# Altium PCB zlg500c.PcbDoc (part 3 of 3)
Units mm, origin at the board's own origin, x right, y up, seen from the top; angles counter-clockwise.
Board outline 135.13 x 130.56 mm, 2 copper layers (Top Layer, Bottom Layer); 79 components, 87 nets, 356 pads, 44 vias.
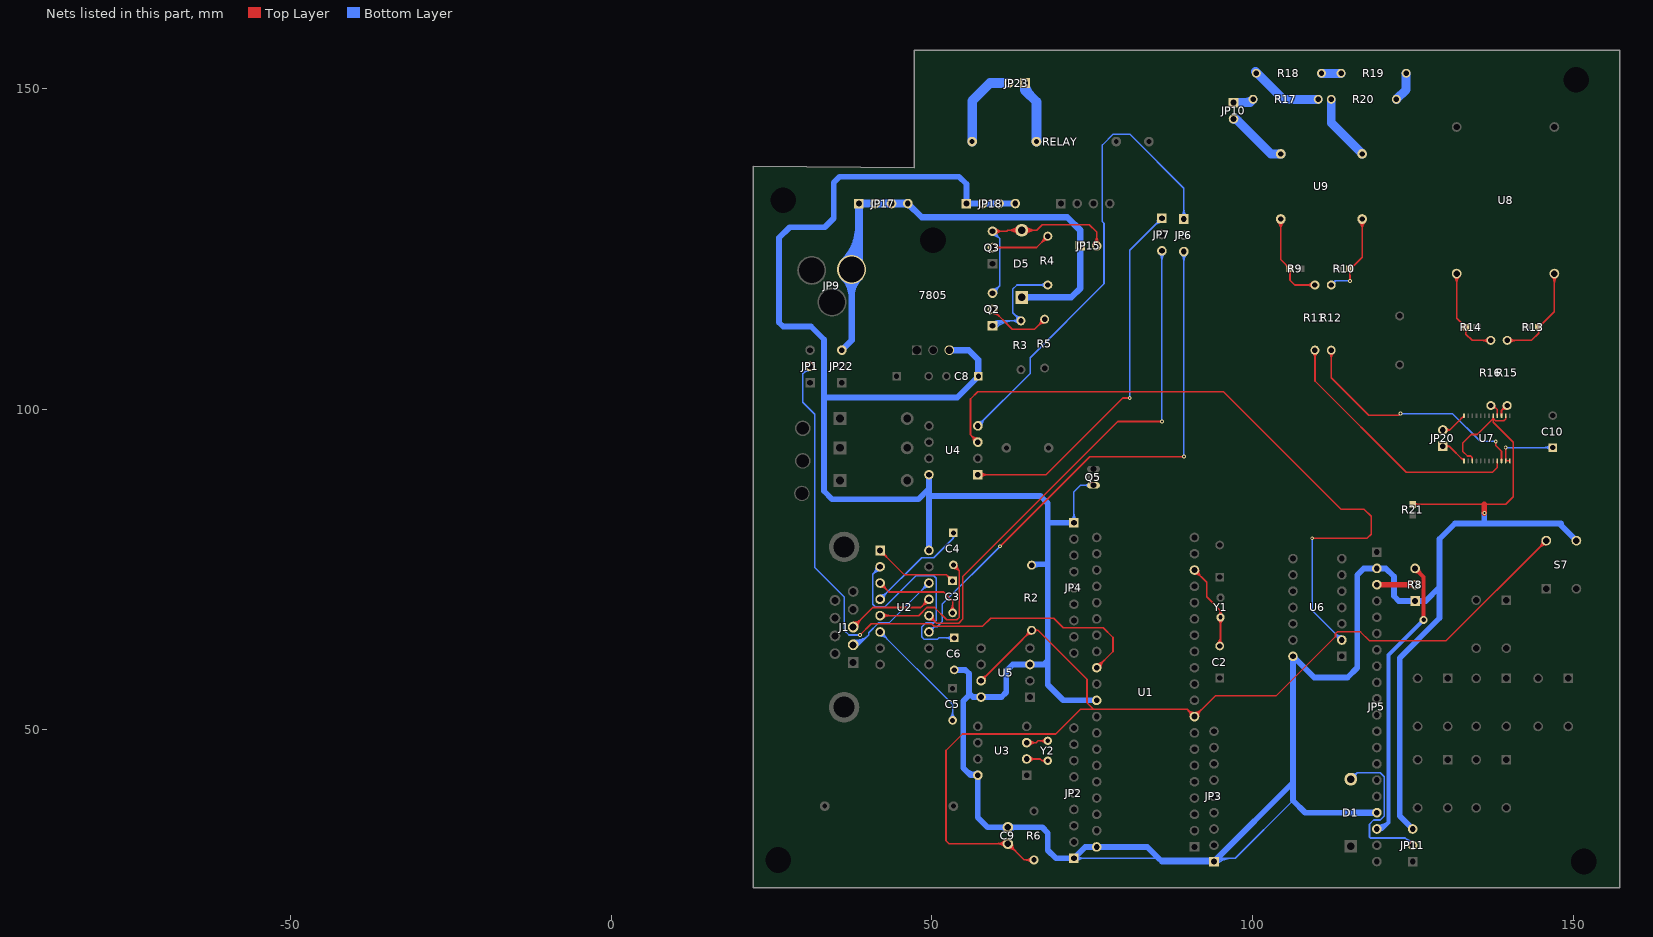
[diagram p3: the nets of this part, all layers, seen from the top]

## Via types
v1: diameter 0.6, hole 0.3, Top Layer to Bottom Layer, 43 vias
v2: diameter 1.27, hole 0.711, Top Layer to Bottom Layer, 1 vias

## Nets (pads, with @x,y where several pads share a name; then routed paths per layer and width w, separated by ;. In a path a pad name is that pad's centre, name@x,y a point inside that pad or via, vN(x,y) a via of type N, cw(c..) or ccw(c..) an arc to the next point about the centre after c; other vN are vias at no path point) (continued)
NetC2_2: C2.2 U1.18 Y1.2 | length 23.8
  Top Layer w0.254: U1.18@90.932,74.307 cw(c90.932,72.803) 91.996,73.866 cw(c93.059,74.93) U1.18@91.555,74.93 ; U1.18@90.932,74.561 cw(c90.932,73.67) 91.562,74.3 cw(c92.192,74.93) U1.18@91.301,74.93 ; U1.18@90.932,74.93 92.837,73.025 92.837,70.739 94.996,68.58 ; C2.2@94.482,63.467 ccw(c93.239,64.709) 94.996,64.709 ; Y1.2@94.626,67.168 cw(c93.733,66.275) 94.996,66.275 cw(c96.259,66.275) Y1.2@95.366,67.168 ; C2.2@94.661,63.287 ccw(c93.853,64.095) 94.996,64.095 ccw(c95.885,64.095) C2.2@95.256,63.467 ; Y1.2@94.684,67.957 ccw(c94.22,68.58) 94.996,68.58 ; C2.2@94.869,63.079 94.869,63.206 94.996,63.206 Y1.2@94.996,67.538 94.996,68.58 ; Y1.2@95.308,67.957 cw(c95.772,68.58) 94.996,68.58
NetC3_1: C3.1 U2.1 | length 20.2
  Top Layer w0.254: U2.1@41.91,77.355 cw(c41.91,75.851) 42.974,76.914 cw(c44.037,77.978) U2.1@42.533,77.978 ; U2.1@41.91,77.609 cw(c41.91,76.718) 42.54,77.348 cw(c43.17,77.978) U2.1@42.279,77.978 ; U2.1@41.91,77.978 45.72,74.168 52.284,74.168 ; C3.1@52.665,73.242 ccw(c51.364,73.248) 52.284,74.168 ; C3.1@52.919,73.24 ccw(c52.221,73.244) 52.715,73.737 ccw(c53.208,74.231) C3.1@53.212,73.533 ; C3.1@53.21,73.787 cw(c53.204,75.088) 52.284,74.168 ; C3.1@53.213,73.239 52.284,74.168
NetC3_2: C3.2 U2.3 | length 24.5
  Top Layer w0.254: U2.3@41.91,72.275 cw(c41.91,70.771) 42.974,71.834 cw(c44.037,72.898) U2.3@42.533,72.898 ; U2.3@41.91,72.529 cw(c41.91,71.638) 42.54,72.268 cw(c43.17,72.898) U2.3@42.279,72.898 ; U2.3@41.91,72.898 43.307,71.501 51.816,71.501 53.213,70.104 C3.2@53.213,68.239 ; 53.213,68.949 cw(c52.503,68.949) 53.005,68.447 ccw(c52.503,68.949) 53.213,68.949 ; 53.213,68.949 ccw(c53.923,68.949) 53.421,68.447 cw(c53.923,68.949) 53.213,68.949 ; 53.213,69.562 cw(c51.89,69.562) 52.826,68.626 ccw(c51.89,69.562) 53.213,69.562 ; 53.213,69.562 ccw(c54.536,69.562) 53.6,68.626 cw(c54.536,69.562) 53.213,69.562
NetC4_1: C4.1 U2.4 | length 21.7
  Bottom Layer w0.254: U2.4@41.91,70.358 48.387,76.835 50.292,76.835 53.34,79.883 ; U2.4@41.91,70.727 ccw(c41.91,71.618) 42.54,70.988 ccw(c43.17,70.358) U2.4@42.279,70.358 ; U2.4@41.91,70.981 ccw(c41.91,72.485) 42.974,71.422 ccw(c44.037,70.358) U2.4@42.533,70.358 ; C4.1@53.34,80.732 53.34,79.883 ; 53.34,79.883 cw(c53.724,79.883) 53.566,80.233 ccw(c53.724,79.883) 53.34,79.883 ; 53.34,79.883 ccw(c52.956,79.883) 53.114,80.233 cw(c52.956,79.883) 53.34,79.883
NetC4_2: C4.2 U2.5 | length 33.1
  Top Layer w0.254: U2.5@41.91,67.818 47.93,67.818 49.2,69.088 50.394,69.088 52.324,67.158 53.873,67.158 54.28,67.564 54.28,74.792 C4.2@53.34,75.732 ; C4.2@53.34,75.184 cw(c53.34,73.861) 54.275,74.796 cw(c55.211,75.732) C4.2@53.888,75.732 ; C4.2@53.34,75.438 cw(c53.34,74.728) 53.842,75.23 cw(c54.344,75.732) C4.2@53.634,75.732 ; 42.801,67.818 cw(c42.801,68.709) 42.171,68.079 ccw(c42.801,68.709) 42.801,67.818 ; 42.801,67.818 ccw(c42.801,66.927) 42.171,67.557 cw(c42.801,66.927) 42.801,67.818 ; 43.414,67.818 cw(c43.414,69.322) 42.351,68.259 ccw(c43.414,69.322) 43.414,67.818 ; 43.414,67.818 ccw(c43.414,66.314) 42.351,67.377 cw(c43.414,66.314) 43.414,67.818
NetC5_2: C5.2 U2.6 | length 25.4
  Bottom Layer w0.254: U2.6@41.91,64.655 cw(c41.91,63.151) 42.974,64.214 cw(c44.037,65.278) U2.6@42.533,65.278 ; U2.6@41.91,64.909 cw(c41.91,64.018) 42.54,64.648 cw(c43.17,65.278) U2.6@42.279,65.278 ; U2.6@41.91,65.278 53.213,53.975 C5.2@53.213,51.475 ; C5.2@52.826,51.862 ccw(c51.89,52.798) 53.213,52.798 ccw(c54.536,52.798) C5.2@53.6,51.862 ; C5.2@53.005,51.683 ccw(c52.503,52.185) 53.213,52.185 ccw(c53.923,52.185) C5.2@53.421,51.683
NetC6_1: C6.1 U2.2 | length 41.7
  Bottom Layer w0.254: U2.2@41.287,75.438 cw(c39.783,75.438) 40.846,74.374 cw(c41.91,73.311) U2.2@41.91,74.815 ; U2.2@41.541,75.438 cw(c40.65,75.438) 41.28,74.808 cw(c41.91,74.178) U2.2@41.91,75.069 ; U2.2@41.91,75.438 40.767,74.295 40.767,69.596 41.148,69.215 42.672,69.215 47.498,74.041 50.292,74.041 50.673,73.66 50.673,67.056 50.292,66.675 49.022,66.675 48.387,66.04 48.387,64.516 48.768,64.135 50.876,64.135 51.09,64.349 C6.1@53.467,64.349 ; C6.1@53.08,63.962 ccw(c52.144,63.026) 52.144,64.349 ccw(c52.144,65.672) C6.1@53.08,64.737 ; C6.1@53.259,64.141 ccw(c52.757,63.639) 52.757,64.349 ccw(c52.757,65.059) C6.1@53.259,64.557
NetC10_1: C10.1 U7.11 U7.12 | length 16.5
  Top Layer w0.254: v1(139.469,94.02) U7.11@139.469,91.948 U7.12@140.119,91.948
  Bottom Layer w0.254: v1(139.469,94.02) C10.1@146.812,94.02 ; 145.489,94.02 cw(c145.489,92.697) 146.425,93.632 ccw(c145.489,92.697) 145.489,94.02 ; 145.489,94.02 ccw(c145.489,95.343) 146.425,94.407 cw(c145.489,95.343) 145.489,94.02 ; 146.102,94.02 cw(c146.102,93.31) 146.604,93.812 ccw(c146.102,93.31) 146.102,94.02 ; 146.102,94.02 ccw(c146.102,94.73) 146.604,94.228 cw(c146.102,94.73) 146.102,94.02
NetD1_1: D1.1 JP11.2 | length 34.7
  Bottom Layer w0.254: D1.1@115.316,42.314 116.309,43.307 ; JP11.2@124.968,32.004 123.825,33.147 118.364,33.147 118.237,33.274 118.237,35.306 118.872,35.941 119.888,35.941 120.523,36.576 120.523,42.672 119.888,43.307 116.309,43.307 ; 116.309,43.307 cw(c115.819,43.797) 115.596,43.141 ccw(c115.819,43.797) 116.309,43.307 ; 116.309,43.307 ccw(c116.799,42.817) 116.143,42.594 cw(c116.799,42.817) 116.309,43.307 ; 123.904,33.068 cw(c122.841,32.004) 124.345,32.004 ccw(c122.841,32.004) 123.904,33.068 ; 123.904,33.068 ccw(c124.968,34.131) 124.968,32.627 cw(c124.968,34.131) 123.904,33.068 ; 124.338,32.634 cw(c123.708,32.004) 124.599,32.004 ccw(c123.708,32.004) 124.338,32.634 ; 124.338,32.634 ccw(c124.968,33.264) 124.968,32.373 cw(c124.968,33.264) 124.338,32.634
NetD5_1: D5.1 JP15.2 Q2.3 Q3.3 | length 56.3
  Top Layer w0.254: Q3.3@59.436,127.762 61.646,127.762 61.796,127.912 D5.1@64.008,127.912 66.317,127.912 67.183,128.778 74.549,128.778 75.692,127.635 JP15.2@75.692,125.476 ; Q3.3@59.697,127.501 cw(c60.327,126.871) 60.327,127.762 cw(c60.327,128.653) Q3.3@59.697,128.023 ; Q3.3@59.877,127.321 cw(c60.94,126.258) 60.94,127.762 cw(c60.94,129.266) Q3.3@59.877,128.203 ; D5.1@63.391,127.295 ccw(c61.9,125.804) 61.9,127.912 ccw(c61.9,130.02) D5.1@63.391,128.529 ; D5.1@63.57,127.474 ccw(c62.514,126.418) 62.514,127.912 ccw(c62.514,129.406) D5.1@63.57,128.35 ; D5.1@64.446,127.474 cw(c65.502,126.418) 65.502,127.912 cw(c65.502,129.406) D5.1@64.446,128.35 ; D5.1@64.625,127.295 cw(c66.116,125.804) 66.116,127.912 cw(c66.116,130.02) D5.1@64.625,128.529 ; JP15.2@75.251,125.917 ccw(c74.188,126.98) 75.692,126.98 ccw(c77.196,126.98) JP15.2@76.133,125.917 ; JP15.2@75.431,125.737 ccw(c74.801,126.367) 75.692,126.367 ccw(c76.583,126.367) JP15.2@75.953,125.737
  Bottom Layer w0.254: Q2.3@59.436,118.11 60.579,119.253 60.579,126.619 Q3.3@59.436,127.762 ; Q2.3@59.436,118.479 ccw(c59.436,119.37) 60.066,118.74 ccw(c60.696,118.11) Q2.3@59.805,118.11 ; Q2.3@59.436,118.733 ccw(c59.436,120.237) 60.5,119.174 ccw(c61.563,118.11) Q2.3@60.059,118.11 ; Q3.3@59.436,127.139 cw(c59.436,125.635) 60.5,126.698 cw(c61.563,127.762) Q3.3@60.059,127.762 ; Q3.3@59.436,127.393 cw(c59.436,126.502) 60.066,127.132 cw(c60.696,127.762) Q3.3@59.805,127.762
NetJP1_2: JP1.2 U1.29 | length 106.2
  Top Layer w0.254: v1(38.786,64.795) 40.538,66.548 49.936,66.548 50.343,66.142 57.887,66.142 59.157,67.412 68.986,67.412 70.485,65.913 76.733,65.913 78.232,64.414 78.232,62.23 U1.29@75.692,59.69 ; 76.322,60.32 cw(c75.692,60.95) 75.692,60.059 ccw(c75.692,60.95) 76.322,60.32 ; 76.322,60.32 ccw(c76.952,59.69) 76.061,59.69 cw(c76.952,59.69) 76.322,60.32 ; 76.756,60.754 cw(c75.692,61.817) 75.692,60.313 ccw(c75.692,61.817) 76.756,60.754 ; 76.756,60.754 ccw(c77.819,59.69) 76.315,59.69 cw(c77.819,59.69) 76.756,60.754
  Bottom Layer w0.254: JP1.2@30.365,106.68 cw(c28.861,106.68) 29.924,105.616 cw(c30.988,104.553) JP1.2@30.988,106.057 ; JP1.2@30.619,106.68 cw(c29.728,106.68) 30.358,106.05 cw(c30.988,105.42) JP1.2@30.988,106.311 ; JP1.2@30.988,106.68 29.845,105.537 29.845,101.117 31.725,99.238 31.725,75.311 36.322,70.714 36.322,65.532 37.059,64.795 v1(38.786,64.795)
NetJP10_1: JP10.1 R17.2 | length 25.1
  Bottom Layer w0.254: JP10.1@97.028,147.828 97.536,148.336 R17.2@100.076,148.336 ; R17.2@99.671,147.931 ccw(c98.693,146.953) 98.693,148.336 ccw(c98.693,149.719) R17.2@99.671,148.741 ; R17.2@99.85,148.11 ccw(c99.306,147.566) 99.306,148.336 ccw(c99.306,149.106) R17.2@99.85,148.562 ; JP10.1@96.93,147.926 cw(c97.919,146.937) 97.919,148.336 ccw(c97.919,146.937) JP10.1@96.93,147.926 ; JP10.1@97.109,147.747 cw(c98.532,146.324) 98.532,148.336 ccw(c98.532,146.324) JP10.1@97.109,147.747 ; JP10.1@97.289,147.567 cw(c99.145,145.711) 99.145,148.336 ccw(c99.145,145.711) JP10.1@97.289,147.567 ; JP10.1@97.469,147.387 cw(c99.758,145.098) 99.758,148.336 ccw(c99.758,145.098) JP10.1@97.469,147.387
  Bottom Layer w1.4: JP10.1@97.028,147.828 99.568,147.828 ; 98.85,147.828 ccw(c98.85,149.562) R17.2@100.076,148.336
NetJP10_2: JP10.2 U9.2 | length 11.3
  Bottom Layer w1.4: JP10.2@97.028,145.288 97.409,145.288 102.87,139.827 U9.2@104.394,139.827 ; JP10.2@97.028,145.238 cw(c97.028,144.197) 97.764,144.933 ccw(c97.028,144.197) JP10.2@97.028,145.238
NetJP20_1: JP20.1 U7.1 | length 7.5
  Top Layer w0.254: JP20.1@129.667,94.234 130.683,94.234 ; U7.1@132.969,91.948 130.683,94.234 ; 130.683,94.234 cw(c130.683,94.751) 130.222,94.517 ccw(c130.683,94.751) 130.683,94.234 ; 130.683,94.234 ccw(c130.683,93.717) 130.222,93.951 cw(c130.683,93.717) 130.683,94.234 ; 132.546,92.371 ccw(c132.969,92.795) 132.969,92.196 cw(c132.969,92.795) 132.546,92.371
NetJP20_2: JP20.2 U7.24 | length 7.8
  Top Layer w0.254: JP20.2@129.667,96.774 130.745,96.774 ; U7.24@132.969,98.998 130.745,96.774 ; 130.745,96.774 cw(c130.745,97.395) 130.207,97.085 ccw(c130.745,97.395) 130.745,96.774 ; 130.745,96.774 ccw(c130.745,96.153) 130.207,96.463 cw(c130.745,96.153) 130.745,96.774 ; 132.546,98.575 cw(c132.969,98.151) 132.969,98.75 ccw(c132.969,98.151) 132.546,98.575
NetJP23_1: JP23.1 RELAY.2 | length 12
  Bottom Layer w1.5: 65.324,148.925 cw(c67.275,150.876) JP23.1@64.516,150.876 64.516,149.733 66.294,147.955 RELAY.2@66.294,141.732
NetJP23_2: JP23.2 RELAY.3 | length 13.2
  Bottom Layer w1.5: RELAY.3@56.261,141.732 56.261,148.082 59.055,150.876 JP23.2@61.976,150.876
NetQ2_1: Q2.1 R3.2 R4.2 | length 40
  Bottom Layer w0.254: Q2.1@59.158,113.308 cw(c60.327,112.139) 60.327,113.792 ; Q2.1@59.338,113.128 cw(c60.94,111.526) 60.94,113.792 ; Q2.1@59.436,113.03 60.198,113.792 ; Q2.1@59.517,112.949 cw(c61.553,110.913) 61.553,113.792 ; Q2.1@59.697,112.769 cw(c62.166,110.3) 62.166,113.792 ; Q2.1@59.877,112.589 cw(c62.78,109.686) 62.78,113.792 ; R3.2@63.308,113.792 ccw(c61.925,113.792) 62.903,114.77 ccw(c63.881,115.748) R3.2@63.881,114.365 ; R3.2@63.476,113.387 ccw(c62.498,112.409) 62.498,113.792 ccw(c62.498,115.175) R3.2@63.476,114.197 ; R3.2@63.562,113.792 ccw(c62.792,113.792) 63.336,114.337 ccw(c63.881,114.881) R3.2@63.881,114.111 ; R3.2@63.655,113.566 ccw(c63.111,113.022) 63.111,113.792 ccw(c63.111,114.562) R3.2@63.655,114.018 ; R4.2@67.667,118.975 ccw(c66.689,117.997) 66.689,119.38 ccw(c66.689,120.763) R4.2@67.667,119.785 ; R4.2@67.846,119.154 ccw(c67.302,118.61) 67.302,119.38 ccw(c67.302,120.15) R4.2@67.846,119.606 ; R4.2@68.072,119.38 63.246,119.38 62.611,118.745 62.611,115.062 R3.2@63.881,113.792 60.198,113.792 ; 60.198,113.792 cw(c59.759,114.231) 59.598,113.632 ccw(c59.759,114.231) 60.198,113.792 ; 60.198,113.792 ccw(c60.637,113.353) 60.038,113.192 cw(c60.637,113.353) 60.198,113.792
NetQ2_2: Q2.2 R5.1 | length 17.2
  Top Layer w0.254: Q2.2@59.436,114.947 cw(c59.436,113.443) 60.5,114.506 cw(c61.563,115.57) Q2.2@60.059,115.57 ; Q2.2@59.436,115.201 cw(c59.436,114.31) 60.066,114.94 cw(c60.696,115.57) Q2.2@59.805,115.57 ; Q2.2@59.436,115.57 62.535,112.471 65.989,112.471 R5.1@67.564,114.046 ; R5.1@66.991,114.046 cw(c65.608,114.046) 66.586,113.068 cw(c67.564,112.09) R5.1@67.564,113.473 ; R5.1@67.245,114.046 cw(c66.475,114.046) 67.019,113.501 cw(c67.564,112.957) R5.1@67.564,113.727
NetQ3_2: Q3.2 R4.1 | length 16.5
  Top Layer w0.254: Q3.2@59.436,125.222 66.294,125.222 R4.1@68.072,127 ; Q3.2@59.697,124.961 cw(c60.327,124.331) 60.327,125.222 cw(c60.327,126.113) Q3.2@59.697,125.483 ; Q3.2@59.877,124.781 cw(c60.94,123.718) 60.94,125.222 cw(c60.94,126.726) Q3.2@59.877,125.663 ; R4.1@67.499,127 cw(c66.116,127) 67.094,126.022 cw(c68.072,125.044) R4.1@68.072,126.427 ; R4.1@67.753,127 cw(c66.983,127) 67.527,126.455 cw(c68.072,125.911) R4.1@68.072,126.681
NetR9_1: R9.1 R11.1 U9.3 | length 24.4
  Top Layer w0.254: U9.3@103.945,129.218 cw(c102.861,128.134) 104.394,128.134 cw(c105.927,128.134) U9.3@104.843,129.218 ; U9.3@104.125,129.398 cw(c103.474,128.747) 104.394,128.747 cw(c105.314,128.747) U9.3@104.663,129.398 ; U9.3@104.394,129.667 104.394,123.356 R9.1@105.83,121.92 105.83,120.103 106.553,119.38 R11.1@109.728,119.38 ; 105.108,122.642 cw(c104.386,121.92) R9.1@105.407,121.92 ; 105.229,122.521 ccw(c105.78,123.073) R9.1@105.78,122.293 ; R9.1@105.566,121.656 cw(c104.93,121.02) 105.83,121.02 cw(c106.731,121.02) R9.1@106.094,121.656 ; R11.1@109.323,118.975 ccw(c108.345,117.997) 108.345,119.38 ccw(c108.345,120.763) R11.1@109.323,119.785 ; R11.1@109.502,119.154 ccw(c108.958,118.61) 108.958,119.38 ccw(c108.958,120.15) R11.1@109.502,119.606
NetR10_2: R10.2 R12.1 U9.4 | length 21.9
  Top Layer w0.254: v1(115.189,120.015) R10.2@115.15,121.92 115.316,121.92 117.094,123.698 U9.4@117.094,129.667 ; R10.2@115.2,122.293 ccw(c115.2,123.474) 116.035,122.639 ; R10.2@115.573,121.92 cw(c116.193,121.92) 115.755,122.359 ; U9.4@116.645,129.218 cw(c115.561,128.134) 117.094,128.134 cw(c118.627,128.134) U9.4@117.543,129.218 ; U9.4@116.825,129.398 cw(c116.174,128.747) 117.094,128.747 cw(c118.014,128.747) U9.4@117.363,129.398 ; 115.161,121.383 cw(c115.34,121.386) 115.294,121.559 ccw(c115.34,121.386) 115.161,121.383 ; 115.161,121.383 ccw(c114.927,121.378) 115.032,121.587 cw(c114.927,121.378) 115.161,121.383
  Bottom Layer w0.254: R12.1@112.268,119.38 112.903,120.015 ; v1(115.189,120.015) 112.903,120.015 ; 112.903,120.015 cw(c112.608,120.31) 112.465,119.918 ccw(c112.608,120.31) 112.903,120.015 ; 112.903,120.015 ccw(c113.198,119.72) 112.806,119.577 cw(c113.198,119.72) 112.903,120.015
NetR11_2: R11.2 U7.9 | length 43.9
  Top Layer w0.254: R11.2@109.323,108.815 cw(c108.345,107.837) 109.728,107.837 cw(c111.111,107.837) R11.2@110.133,108.815 ; R11.2@109.502,108.994 cw(c108.958,108.45) 109.728,108.45 cw(c110.498,108.45) R11.2@109.954,108.994 ; R11.2@109.728,109.22 109.728,104.394 123.952,90.17 137.414,90.17 138.169,90.925 U7.9@138.169,91.948
NetR12_2: R12.2 U7.10 | length 41.1
  Top Layer w0.254: R12.2@111.863,108.815 cw(c110.885,107.837) 112.268,107.837 cw(c113.651,107.837) R12.2@112.673,108.815 ; R12.2@112.042,108.994 cw(c111.498,108.45) 112.268,108.45 cw(c113.038,108.45) R12.2@112.494,108.994 ; R12.2@112.268,109.22 112.268,104.902 118.11,99.06 122.809,99.06 v1(123.063,99.314) ; v1(137.922,94.996) 137.922,94.361 138.819,93.464 U7.10@138.819,91.948
  Bottom Layer w0.254: v1(123.063,99.314) 131.191,99.314 135.509,94.996 v1(137.922,94.996)
NetR13_1: R13.1 R15.1 U8.2 | length 25.9
  Top Layer w0.254: R15.1@139.7,110.744 143.51,110.744 144.614,111.848 R13.1@144.614,112.776 147.066,115.228 U8.2@147.066,121.158 U8.2@147.066,121.285 ; R15.1@139.926,110.518 cw(c140.47,109.974) 140.47,110.744 cw(c140.47,111.514) R15.1@139.926,110.97 ; R15.1@140.105,110.339 cw(c141.083,109.361) 141.083,110.744 cw(c141.083,112.127) R15.1@140.105,111.149 ; R13.1@144.35,112.512 cw(c143.713,111.876) 144.614,111.876 cw(c145.514,111.876) R13.1@144.878,112.512 ; R13.1@144.664,113.149 ccw(c144.664,113.929) 145.215,113.377 ; R13.1@145.037,112.776 cw(c146.058,112.776) 145.336,113.498 ; U8.2@146.617,120.709 cw(c145.533,119.625) 147.066,119.625 cw(c148.599,119.625) U8.2@147.515,120.709 ; U8.2@146.797,120.889 cw(c146.146,120.238) 147.066,120.238 cw(c147.986,120.238) U8.2@147.335,120.889
NetR14_2: R14.2 R16.1 U8.1 | length 24.5
  Top Layer w0.254: U8.1@131.377,120.709 cw(c130.293,119.625) 131.826,119.625 cw(c133.359,119.625) U8.1@132.275,120.709 ; U8.1@131.557,120.889 cw(c130.906,120.238) 131.826,120.238 cw(c132.746,120.238) U8.1@132.095,120.889 ; U8.1@131.826,121.285 U8.1@131.826,121.158 131.826,114.212 R14.2@133.262,112.776 133.262,111.721 134.239,110.744 R16.1@137.16,110.744 ; 132.54,113.498 cw(c131.818,112.776) R14.2@132.839,112.776 ; 132.661,113.377 ccw(c133.212,113.929) R14.2@133.212,113.149 ; R14.2@132.998,112.512 cw(c132.362,111.876) 133.262,111.876 cw(c134.163,111.876) R14.2@133.526,112.512 ; R16.1@136.755,110.339 ccw(c135.777,109.361) 135.777,110.744 ccw(c135.777,112.127) R16.1@136.755,111.149 ; R16.1@136.934,110.518 ccw(c136.39,109.974) 136.39,110.744 ccw(c136.39,111.514) R16.1@136.934,110.97
NetR15_2: R15.2 U7.15 | length 6.7
  Top Layer w0.254: U7.15@138.819,98.998 138.819,99.83 139.573,100.584 R15.2@139.7,100.584 ; 138.756,99.767 cw(c139.413,99.109) 139.59,100.022 ccw(c139.413,99.109) 138.756,99.767 ; 138.812,99.823 ccw(c138.05,100.584) 139.127,100.584 cw(c138.05,100.584) 138.812,99.823 ; 139.093,100.104 cw(c139.523,99.675) 139.639,100.271 ccw(c139.523,99.675) 139.093,100.104
NetR16_2: R16.2 U7.16 | length 4.7
  Top Layer w0.254: R16.2@137.16,100.584 137.541,100.584 138.169,99.956 U7.16@138.169,98.998 ; R16.2@137.249,100.278 cw(c137.476,99.49) 138.055,100.07 ccw(c137.476,99.49) R16.2@137.249,100.278 ; R16.2@137.733,100.584 ccw(c138.197,100.584) 137.869,100.256 cw(c138.197,100.584) R16.2@137.733,100.584
NetR17_1: R17.1 R18.2 | length 11.7
  Bottom Layer w0.254: R18.2@100.559,152.552 100.559,152.4 R18.2@100.584,152.4
  Bottom Layer w1.4: R18.2@100.457,152.654 100.559,152.552 100.647,152.463 104.775,148.336 R17.1@110.236,148.336
NetR18_1: R18.1 R19.2 | length 3
  Bottom Layer w1.4: R18.1@110.744,152.4 R19.2@113.792,152.4
NetR19_1: R19.1 R20.1 | length 5.2
  Top Layer w0.254: R20.1@122.428,148.336 R20.1@122.428,148.844
  Bottom Layer w1.4: R20.1@122.428,148.336 123.952,149.86 R19.1@123.952,152.4
NetR20_2: R20.2 U9.1 | length 10.5
  Bottom Layer w1.4: R20.2@112.268,148.336 112.268,144.653 U9.1@117.094,139.827
NetU3_2: U3.2 Y2.2 | length 13
  Top Layer w0.254: U3.2@64.77,45.466 66.904,45.466 67.184,45.186 Y2.2@68.072,45.186 ; 65.661,45.466 cw(c65.661,46.357) 65.031,45.727 ccw(c65.661,46.357) 65.661,45.466 ; 65.661,45.466 ccw(c65.661,44.575) 65.031,45.205 cw(c65.661,44.575) 65.661,45.466 ; 66.274,45.466 cw(c66.274,46.97) 65.211,45.907 ccw(c66.274,46.97) 66.274,45.466 ; 66.274,45.466 ccw(c66.274,43.962) 65.211,45.025 cw(c66.274,43.962) 66.274,45.466 ; 67.184,45.186 cw(c67.184,44.693) 67.615,44.932 ccw(c67.184,44.693) 67.184,45.186 ; 67.184,45.186 ccw(c67.184,45.679) 67.615,45.44 cw(c67.184,45.679) 67.184,45.186
NetU3_3: U3.3 Y2.1 | length 14.9
  Top Layer w0.254: U3.3@64.77,48.006 66.269,48.006 ; Y2.1@68.072,48.286 66.549,48.286 66.269,48.006 ; 65.658,48.006 cw(c65.658,48.889) 65.032,48.266 ccw(c65.658,48.889) 65.658,48.006 ; 65.658,48.006 ccw(c65.658,47.123) 65.032,47.746 cw(c65.658,47.123) 65.658,48.006 ; 66.269,48.006 cw(c66.269,49.497) 65.212,48.445 ccw(c66.269,49.497) 66.269,48.006 ; 66.269,48.006 ccw(c66.269,46.515) 65.212,47.567 cw(c66.269,46.515) 66.269,48.006 ; 66.809,48.286 cw(c66.809,47.023) 67.702,47.916 ccw(c66.809,47.023) 66.809,48.286 ; 66.809,48.286 ccw(c66.809,49.549) 67.702,48.656 cw(c66.809,49.549) 66.809,48.286
NetU4_3: U4.3 U6.2 | length 119.5
  Top Layer w0.254: U4.3@56.527,94.869 ccw(c55.023,94.869) 56.086,95.933 ccw(c57.15,96.996) U4.3@57.15,95.492 ; U4.3@56.781,94.869 ccw(c55.89,94.869) 56.52,95.499 ccw(c57.15,96.129) U4.3@57.15,95.238 ; U4.3@57.15,94.869 56.007,96.012 56.007,101.6 57.15,102.743 95.453,102.743 113.817,84.379 117.424,84.379 118.491,83.312 118.491,80.518 117.856,79.883 v1(109.296,79.883)
  Bottom Layer w0.254: v1(109.296,79.883) 109.296,68.631 U6.2@113.919,64.008 ; 112.855,65.072 cw(c111.792,64.008) 113.296,64.008 ccw(c111.792,64.008) 112.855,65.072 ; 112.855,65.072 ccw(c113.919,66.135) 113.919,64.631 cw(c113.919,66.135) 112.855,65.072 ; 113.289,64.638 cw(c112.659,64.008) 113.55,64.008 ccw(c112.659,64.008) 113.289,64.638 ; 113.289,64.638 ccw(c113.919,65.268) 113.919,64.377 cw(c113.919,65.268) 113.289,64.638
PC-RXD: J1.2 U2.14 | length 29.9
  Bottom Layer w0.254: J1.2@37.682,62.974 ccw(c37.818,64.139) 38.648,63.31 ; J1.2@37.712,63.226 ccw(c37.896,64.803) 39.019,63.681 ; J1.2@37.717,63.27 38.608,63.27 ; J1.2@37.741,63.479 ccw(c37.973,65.468) 39.39,64.052 ; J1.2@37.771,63.731 ccw(c38.051,66.133) 39.761,64.423 ; J1.2@37.8,63.983 ccw(c38.129,66.797) 40.132,64.794 ; U2.14@48.907,72.898 cw(c47.403,72.898) 48.466,71.834 cw(c49.53,70.771) U2.14@49.53,72.275 ; U2.14@49.161,72.898 cw(c48.27,72.898) 48.9,72.268 cw(c49.53,71.638) U2.14@49.53,72.529 ; U2.14@49.53,72.898 43.307,66.675 41.656,66.675 40.132,65.151 40.132,64.794 ; 38.608,63.27 cw(c38.608,63.464) 38.419,63.423 ccw(c38.608,63.464) 38.608,63.27 ; 38.608,63.27 ccw(c38.608,63.076) 38.419,63.117 cw(c38.608,63.076) 38.608,63.27 ; 38.608,63.27 40.132,64.794
PC-TXD: J1.3 U2.13 | length 21.8
  Top Layer w0.254: J1.3@37.717,66.04 40.765,69.088 48.26,69.088 U2.13@49.53,70.358 ; J1.3@37.717,66.504 ccw(c37.717,67.624) 38.509,66.832 ccw(c39.301,66.04) J1.3@38.181,66.04 ; J1.3@37.717,66.758 ccw(c37.717,68.491) 38.943,67.266 ccw(c40.168,66.04) J1.3@38.435,66.04 ; U2.13@48.907,70.358 cw(c47.403,70.358) 48.466,69.294 cw(c49.53,68.231) U2.13@49.53,69.735 ; U2.13@49.161,70.358 cw(c48.27,70.358) 48.9,69.728 cw(c49.53,69.098) U2.13@49.53,69.989
RESET: C9.1 R2.1 R6.2 S7.4 U1.9 U5.7 | length 213.1
  Top Layer w0.254: U5.7@57.658,57.658 58.547,58.547 ; U5.7@57.742,58.275 ccw(c57.87,59.224) 58.547,58.547 ; U5.7@58.275,57.742 cw(c59.224,57.87) 58.547,58.547 ; C9.1@61.355,31.764 ccw(c60.164,30.573) 60.164,32.258 ccw(c60.164,33.943) C9.1@61.355,32.752 ; C9.1@61.535,31.944 ccw(c60.777,31.186) 60.777,32.258 ccw(c60.777,33.33) C9.1@61.535,32.572 ; C9.1@61.849,31.56 cw(c61.849,29.875) 63.041,31.066 cw(c64.232,32.258) C9.1@62.547,32.258 ; C9.1@61.849,31.814 cw(c61.849,30.742) 62.607,31.5 cw(c63.365,32.258) C9.1@62.293,32.258 ; 64.135,64.084 58.623,58.572 ; R2.1@64.959,65.532 cw(c63.576,65.532) 64.554,64.554 cw(c65.532,63.576) R2.1@65.532,64.959 ; R2.1@65.213,65.532 cw(c64.443,65.532) 64.987,64.987 cw(c65.532,64.443) R2.1@65.532,65.213 ; R6.2@65.508,29.313 ccw(c64.53,28.335) 64.53,29.718 ccw(c64.53,31.101) R6.2@65.508,30.123 ; R6.2@65.687,29.492 ccw(c65.143,28.948) 65.143,29.718 ccw(c65.143,30.488) R6.2@65.687,29.944 ; R6.2@65.913,29.718 64.389,29.718 C9.1@61.849,32.258 52.654,32.258 52.197,32.715 52.197,46.787 54.762,49.352 69.291,49.352 73.152,53.213 75.184,53.213 ; S7.4@145.161,79.502 cw(c143.628,79.502) 144.712,78.418 cw(c145.796,77.334) S7.4@145.796,78.867 ; S7.4@145.415,79.502 cw(c144.495,79.502) 145.146,78.852 cw(c145.796,78.201) S7.4@145.796,79.121 ; S7.4@145.796,79.502 130.175,63.881 118.237,63.881 116.84,65.278 113.182,65.278 112.928,65.024 112.928,64.565 103.659,55.296 94.158,55.296 U1.9@90.932,52.07 89.789,53.213 75.184,53.213 ; 58.547,58.547 58.598,58.547 58.623,58.572 ; 58.623,58.572 58.598,58.598 R2.1@65.532,65.532 66.548,65.532 ; 66.548,65.532 cw(c66.548,66.146) 66.022,65.828 ccw(c66.548,66.146) 66.548,65.532 ; 66.548,65.532 ccw(c66.548,64.918) 66.022,65.236 cw(c66.548,64.918) 66.548,65.532 ; 66.548,65.532 74.168,57.912 74.168,54.229 75.184,53.213 ; 89.868,53.134 cw(c88.805,52.07) 90.309,52.07 ccw(c88.805,52.07) 89.868,53.134 ; 89.868,53.134 ccw(c90.932,54.197) U1.9@90.932,52.693 ; 89.868,53.134 ccw(c90.932,54.197) U1.9@90.932,52.693 ; 90.302,52.7 cw(c89.672,52.07) 90.563,52.07 ccw(c89.672,52.07) 90.302,52.7 ; 90.302,52.7 ccw(c90.932,53.33) U1.9@90.932,52.439 ; 90.302,52.7 ccw(c90.932,53.33) U1.9@90.932,52.439 ; U1.9@90.932,52.439 ccw(c90.932,53.33) 91.562,52.7 ; U1.9@90.932,52.439 ccw(c90.932,53.33) 91.562,52.7 ; U1.9@90.932,52.693 ccw(c90.932,54.197) 91.996,53.134 ; U1.9@90.932,52.693 ccw(c90.932,54.197) 91.996,53.134 ; 91.562,52.7 ccw(c92.192,52.07) 91.301,52.07 cw(c92.192,52.07) 91.562,52.7 ; 91.996,53.134 ccw(c93.059,52.07) 91.555,52.07 cw(c93.059,52.07) 91.996,53.134
RS-232R: JP7.3 U2.12 | length 91.6
  Top Layer w0.254: U2.12@49.53,67.818 50.698,66.65 54.153,66.65 54.788,67.285 54.788,73.914 78.969,98.095 v1(85.852,98.095) ; 50.16,67.188 cw(c50.79,67.818) 49.899,67.818 ccw(c50.79,67.818) 50.16,67.188 ; 50.16,67.188 ccw(c49.53,66.558) 49.53,67.449 cw(c49.53,66.558) 50.16,67.188 ; 50.594,66.754 cw(c51.657,67.818) 50.153,67.818 ccw(c51.657,67.818) 50.594,66.754 ; 50.594,66.754 ccw(c49.53,65.691) 49.53,67.195 cw(c49.53,65.691) 50.594,66.754
  Bottom Layer w0.254: JP7.3@85.411,124.273 cw(c84.348,123.21) 85.852,123.21 cw(c87.356,123.21) JP7.3@86.293,124.273 ; JP7.3@85.591,124.453 cw(c84.961,123.823) 85.852,123.823 cw(c86.743,123.823) JP7.3@86.113,124.453 ; v1(85.852,98.095) JP7.3@85.852,124.714
RS-232T: JP6.3 U2.11 | length 93.7
  Top Layer w0.254: v1(60.63,78.638) 74.6,92.608 v1(89.281,92.608)
  Bottom Layer w0.254: U2.11@49.53,65.278 50.343,66.091 ; U2.11@49.659,65.888 ccw(c49.813,66.62) 50.343,66.091 ; U2.11@50.14,65.407 cw(c50.872,65.561) 50.343,66.091 ; v1(60.63,78.638) 51.613,69.621 51.613,66.904 50.8,66.091 50.343,66.091 ; v1(89.281,92.608) JP6.3@89.281,124.587 ; 89.281,123.083 cw(c90.785,123.083) 89.722,124.146 ccw(c90.785,123.083) 89.281,123.083 ; 89.281,123.083 ccw(c87.777,123.083) 88.84,124.146 cw(c87.777,123.083) 89.281,123.083 ; 89.281,123.696 cw(c90.172,123.696) 89.542,124.326 ccw(c90.172,123.696) 89.281,123.696 ; 89.281,123.696 ccw(c88.39,123.696) 89.02,124.326 cw(c88.39,123.696) 89.281,123.696
RS-485R: JP7.1 U4.1 | length 66.3
  Top Layer w0.254: U4.1@57.15,89.789 67.793,89.789 79.756,101.752 v1(80.848,101.752) ; U4.1@57.411,89.528 cw(c58.041,88.898) 58.041,89.789 cw(c58.041,90.68) U4.1@57.411,90.05 ; U4.1@57.591,89.348 cw(c58.654,88.285) 58.654,89.789 cw(c58.654,91.293) U4.1@57.591,90.23
  Bottom Layer w0.254: v1(80.848,101.752) 80.848,124.79 JP7.1@85.852,129.794 ; JP7.1@85.229,129.794 cw(c83.725,129.794) 84.788,128.73 cw(c85.852,127.667) JP7.1@85.852,129.171 ; JP7.1@85.483,129.794 cw(c84.592,129.794) 85.222,129.164 cw(c85.852,128.534) JP7.1@85.852,129.425
RS-485T: JP6.1 U4.4 | length 81.3
  Bottom Layer w0.254: U4.4@57.15,97.409 65.303,105.562 65.303,108.052 76.835,119.583 76.835,129.007 76.581,129.261 76.581,141.224 78.232,142.875 80.874,142.875 89.281,134.468 JP6.1@89.281,129.667 ; U4.4@57.15,97.778 ccw(c57.15,98.669) 57.78,98.039 ccw(c58.41,97.409) U4.4@57.519,97.409 ; U4.4@57.15,98.032 ccw(c57.15,99.536) 58.214,98.473 ccw(c59.277,97.409) U4.4@57.773,97.409 ; JP6.1@88.84,130.108 ccw(c87.777,131.171) 89.281,131.171 ccw(c90.785,131.171) JP6.1@89.722,130.108 ; JP6.1@89.02,129.928 ccw(c88.39,130.558) 89.281,130.558 ccw(c90.172,130.558) JP6.1@89.542,129.928
VCC: 7805.2 C6.2 C8.1 C9.2 JP2.1 JP3.1 JP4.1 JP5.2 JP5.17 JP11.3 JP18.1 JP18.2 JP18.3 JP18.4 Q5.3 R2.2 R8.1 R21.2 S7.3 U1.31 U1.40 U2.16 U3.8 U4.8 U5.3 U5.8 U6.14 U7.3 U7.14 U7.17 | length 606
  Top Layer w0.254: R21.2@124.968,85.178 136.144,85.178 139.458,85.178 140.64,86.36 140.64,94.872 137.519,97.993 137.519,98.552 ; R21.2@125.232,84.914 cw(c125.868,84.277) 125.868,85.178 cw(c125.868,86.078) R21.2@125.232,85.442 ; U7.3@134.269,91.948 134.269,92.456 134.015,92.71 133.502,92.71 132.791,93.421 132.791,94.742 134.112,96.063 135.03,96.063 137.519,98.552 ; U7.17@137.519,98.998 137.519,98.552 ; U7.14@139.469,98.998 139.469,98.473 139.192,98.196 137.875,98.196 137.519,98.552 ; 137.372,98.405 ccw(c137.023,98.753) 137.516,98.753 cw(c137.023,98.753) 137.372,98.405 ; U7.17@137.522,98.753 ccw(c138.015,98.753) 137.666,98.405 cw(c138.015,98.753) U7.17@137.522,98.753
  Top Layer w0.9: v1(136.144,83.82) 136.144,85.178
  Bottom Layer w0.254: JP4.1@71.695,82.737 ccw(c70.632,83.8) 72.136,83.8 ccw(c73.64,83.8) JP4.1@72.577,82.737 ; JP4.1@71.875,82.557 ccw(c71.245,83.187) 72.136,83.187 ccw(c73.027,83.187) JP4.1@72.397,82.557 ; JP2.1@72.136,29.972 85.344,29.972 93.98,29.972 94.488,29.972 97.282,29.972 106.299,38.989 ; JP4.1@72.136,82.296 72.136,87.122 73.152,88.138 Q5.3@75.184,88.138 ; JP2.1@72.397,29.711 cw(c73.027,29.081) 73.027,29.972 cw(c73.027,30.863) JP2.1@72.397,30.233 ; JP2.1@72.577,29.531 cw(c73.64,28.468) 73.64,29.972 cw(c73.64,31.476) JP2.1@72.577,30.413 ; Q5.3@74.42,87.874 ccw(c73.783,87.238) 73.783,88.138 ccw(c73.783,89.038) Q5.3@74.42,88.402 ; JP3.1@93.882,29.562 cw(c94.871,28.573) 94.871,29.972 ; JP3.1@94.061,29.383 cw(c95.484,27.96) 95.484,29.972 ; JP3.1@94.241,29.203 cw(c96.097,27.347) 96.097,29.972 ; JP3.1@94.421,29.023 cw(c96.71,26.734) 96.71,29.972 ; 91.25,29.972 cw(c91.25,26.734) 93.539,29.023 ccw(c91.25,26.734) 91.25,29.972 ; 91.863,29.972 cw(c91.863,27.347) 93.719,29.203 ccw(c91.863,27.347) 91.863,29.972 ; 92.476,29.972 cw(c92.476,27.96) 93.899,29.383 ccw(c92.476,27.96) 92.476,29.972 ; 93.089,29.972 cw(c93.089,28.573) 94.078,29.562 ccw(c93.089,28.573) 93.089,29.972
  Bottom Layer w0.9: U2.16@49.53,77.978 49.53,86.487 ; U4.8@49.53,89.789 49.53,87.63 ; C6.2@53.467,59.349 55.205,59.349 55.753,58.801 55.753,55.753 55.942,55.564 ; 55.436,43.497 ccw(c56.449,44.511) U3.8@57.029,43.2 ; C8.1@57.237,105.156 53.935,101.854 33.147,101.854 ; C9.2@61.584,34.533 ccw(c60.944,33.893) 60.944,34.798 ccw(c60.944,35.703) C9.2@61.584,35.063 ; C9.2@62.114,34.533 cw(c62.754,33.893) 62.754,34.798 cw(c62.754,35.703) C9.2@62.114,35.063 ; JP18.4@62.992,132.08 JP18.3@60.452,132.08 JP18.2@57.912,132.08 JP18.1@55.372,132.08 55.372,135.128 54.229,136.271 35.56,136.271 34.671,135.382 34.671,129.794 33.274,128.397 27.813,128.397 26.162,126.746 26.162,113.538 26.797,112.903 31.115,112.903 33.147,110.871 33.147,101.854 ; R2.2@65.532,75.692 65.659,75.819 68.072,75.819 ; R2.2@65.709,75.515 cw(c66.442,74.782) 66.442,75.819 ; JP4.1@72.136,82.296 68.072,82.296 ; JP2.1@72.263,29.845 JP2.1@72.136,29.972 ; U1.31@75.692,54.61 70.485,54.61 68.072,57.023 68.072,60.833 ; 106.299,41.529 106.299,38.989 108.204,37.084 115.951,37.084 ; 106.299,43.688 106.299,41.783 94.488,29.972 JP3.1@93.98,29.464 85.852,29.464 85.344,29.972 83.566,31.75 U1.40@75.692,31.75 73.914,31.75 JP2.1@72.136,29.972 ; U6.14@106.299,61.468 109.601,58.166 114.808,58.166 116.332,59.69 116.332,74.168 117.348,75.184 JP5.2@119.38,75.184 120.777,75.184 122.047,73.914 122.047,70.866 122.809,70.104 R8.1@125.349,70.104 127,70.104 129.159,72.263 ; JP11.3@124.968,34.544 122.936,36.576 122.936,61.214 129.159,67.437 129.159,72.263 ; v1(136.144,83.82) 136.144,82.169 ; S7.3@150.495,79.502 148.082,81.915 148.082,82.169 136.144,82.169 ; 33.147,101.854 33.147,87.249 34.417,85.979 47.879,85.979 49.53,87.63 ; 49.53,86.487 66.929,86.487 68.072,85.344 68.072,82.296 ; 49.53,86.487 49.53,87.63 ; 55.942,55.564 56.388,55.118 U5.8@57.658,55.118 60.833,55.118 61.595,55.88 61.595,59.182 62.611,60.198 U5.3@65.278,60.198 67.437,60.198 68.072,60.833 ; 55.942,55.564 54.864,54.486 54.864,44.069 56.007,42.926 U3.8@57.15,42.926 57.15,36.322 58.674,34.798 C9.2@61.849,34.798 67.183,34.798 68.072,33.909 68.072,31.242 69.342,29.972 JP2.1@72.136,29.972 ; 68.072,60.833 68.072,75.819 ; 68.072,75.819 68.072,82.296 ; 129.159,72.263 129.159,79.756 131.572,82.169 136.144,82.169
  Bottom Layer w1: 7805.2@52.705,109.22 55.753,109.22 57.237,107.736 C8.1@57.237,105.156 ; 106.299,43.434 U6.14@106.299,61.468 ; 115.951,37.084 JP5.17@119.38,37.084
VCC-12: D5.2 JP9.3 JP15.1 JP17.1 JP17.2 JP17.3 JP17.4 JP22.3 | length 100
  Bottom Layer w0.254: JP9.3@37.465,121.793 37.465,122.733 38.405,122.733 JP9.3@38.608,122.936
  Bottom Layer w1: JP22.3@35.941,109.22 37.465,110.744 JP9.3@37.465,121.793 ; JP9.3@36.219,120.547 cw(c33.211,117.539) 37.465,117.539 cw(c41.719,117.539) JP9.3@38.711,120.547 ; JP17.4@46.228,132.08 48.387,129.921 71.12,129.921 73.152,127.889 JP15.1@73.152,125.476 73.152,118.872 71.732,117.452 D5.2@64.008,117.452 ; 65.215,117.452 cw(c65.215,118.659) 64.362,117.806 ccw(c65.215,118.659) 65.215,117.452 ; 65.215,117.452 ccw(c65.215,116.245) 64.362,117.098 cw(c65.215,116.245) 65.215,117.452
  Bottom Layer w1.25: JP9.3@36.307,122.951 ccw(c30.753,128.505) 38.608,128.505 ; JP9.3@37.191,122.067 ccw(c33.771,125.487) 38.608,125.487 ; JP9.3@38.608,122.936 JP17.1@38.608,132.08 JP17.2@41.148,132.08 JP17.3@43.688,132.08 JP17.4@46.228,132.08
VEE: JP5.18 R8.3 | length 54.5
  Top Layer w0.6: R8.3@125.349,74.734 cw(c125.349,73.648) 126.117,74.416 cw(c126.885,75.184) R8.3@125.799,75.184 ; R8.3@125.349,75.184 126.67,73.863 v2(126.67,67.158)
  Bottom Layer w0.6: JP5.18@119.38,34.544 120.193,34.544 ; v2(126.67,67.158) 121.209,61.697 121.209,35.56 ; 120.193,34.544 cw(c120.193,35.053) 119.761,34.783 ccw(c120.193,35.053) 120.193,34.544 ; 120.193,34.544 ccw(c120.193,34.035) 119.761,34.305 cw(c120.193,34.035) 120.193,34.544 ; 120.193,34.544 121.209,35.56 ; 121.209,35.56 cw(c119.769,37) 119.45,34.988 ccw(c119.769,37) 121.209,35.56 ; JP5.18@119.357,34.396 ccw(c119.541,35.562) 120.376,34.727 cw(c119.541,35.562) JP5.18@119.357,34.396
VO: JP5.3 R8.2 | length 6
  Top Layer w0.9: JP5.3@119.38,72.644 R8.2@125.349,72.644
pads on no net: 7805.4 J1.1 J1.4 J1.6 J1.7 J1.8 J1.9 J1.10 J1.11 JP1.1 JP9.1 JP22.1 S1.1 S1.2 S2.1 S2.2 S3.1 S3.2 S4.1 S4.2 S5.1 S5.2 S6.1 S6.2 S7.1 S7.2 U1.30 U2.7 U2.8 U2.9 U2.10 U6.3 U6.4 U6.5 U6.6 U6.8 U6.9 U6.10 U6.11 U6.12 U6.13 U7.2 U7.18 U7.20 U7.21 U7.22 U8.3 U8.4

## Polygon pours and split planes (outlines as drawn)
GND on Top Layer (hatched 90Degree grid 0.508 track 0.203, remove dead copper): 22.733,137.668 22.733,25.4 156.972,25.4 156.972,89.281 107.315,89.281 107.315,105.664 92.964,105.664 92.964,132.207 90.198,134.973 23.241,134.973
GND on Bottom Layer (hatched 90Degree grid 0.508 track 0.203, remove dead copper): 22.225,137.414 22.225,25.654 156.718,25.654 156.718,89.535 110.49,89.535 107.315,92.71 107.315,101.6 104.394,104.521 92.837,104.521 92.837,132.207 90.297,134.747 22.225,134.747

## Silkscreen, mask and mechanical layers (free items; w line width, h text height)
Top Overlay:
  text "5V" at 53.086,131.318 h0.76 r180
  text "12V" at 40.386,130.175 h0.76 r180
  text "GND" at 69.85,130.048 h0.76 r180
  text "-" at 76.708,128.651 h1.52 r180
  text "+" at 71.374,127.127 h1.52
  text "1k" at 68.453,122.428 h0.82 r90
  text "RS232/RS485" at 83.566,120.269 h1.52 r90
  text "1k" at 67.691,109.855 h0.52 r90
  text "5.1k" at 64.389,108.585 h0.82 r90
  text "ISP" at 29.083,107.696 h0.82 r90
  text "0.1uF" at 54.61,103.632 h0.76 r90
  text "0.33uF" at 47.117,102.616 h0.76 r90
  text "ON/OFF" at 39.624,102.108 h1.52 r90
  text "LED" at 123.317,83.312 h0.82 r90
  text "0.1uF" at 54.991,78.74 h0.76 r180
  text "10K" at 66.167,69.088 h1.52 r90
  text "7404" at 110.617,65.278 h1.52 r90
  text "X5045" at 61.849,56.896 h1 r90
  text "DS1302" at 60.071,49.911 h1.02 r270
  text "IN4004" at 114.808,36.195 h0.52 r90
  text "+" at 59.69,34.798 h0.92 r90
  text "4.7k" at 66.167,32.766 h0.52 r90
  text "10uf" at 59.563,31.242 h0.52 r90
  text "Backlight" at 128.143,28.194 h0.82 r90
Bottom Overlay:
  text "0.1uF" at 53.848,70.485 h0.76 r180
  text "RS232/RS485" at 65.278,69.215 h1.02 r89.2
